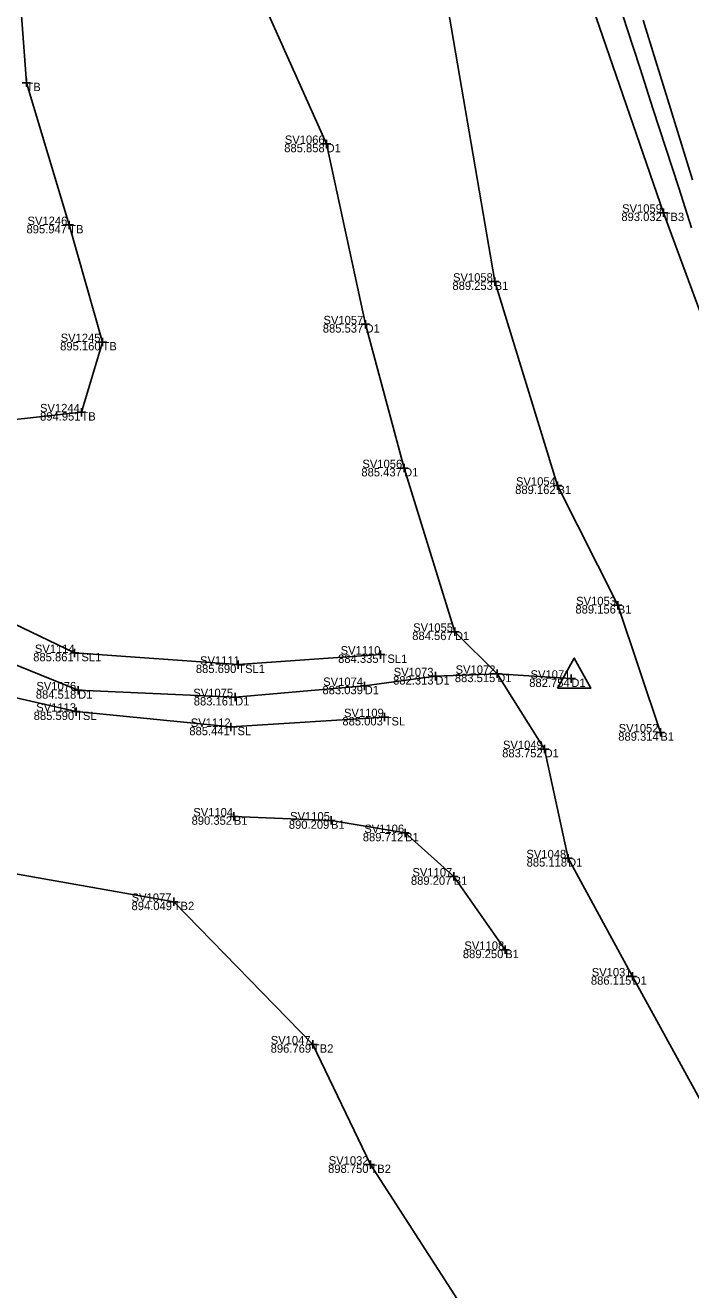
# Model space of a CAD drawing. Extents: x 1918148 to 1919797, y 624701 to 627089.
# Drawn here: x 1919158.7 to 1919238.3, y 625555 to 625706.2 of the extents above; entities that cross this region are included whole.
import ezdxf

# ---------------------------------------------------------------- set-up
doc = ezdxf.new("R2010")
doc.units = 0
for name, color, linetype in [('DR_X_Ditch', 7, 'Continuous'), ('LT_X_Control_Center', 7, 'Continuous'), ('PV_X_EOP', 7, 'Continuous'), ('PV_X_Shoulder_Aggregate', 7, 'Continuous'), ('SV_X_Break_Lines', 7, 'Continuous'), ('SV_X_Shot_Marker', 7, 'Continuous'), ('SV_X_Text_Comment', 7, 'Continuous'), ('SV_X_Text_Elevation', 7, 'Continuous'), ('SV_X_Text_Name', 7, 'Continuous'), ('SV_X_Toe_of_Slope', 7, 'Continuous'), ('SV_X_Top_of_Bank', 7, 'Continuous')]:
    doc.layers.add(name, color=color, linetype=linetype)

msp = doc.modelspace()

# ---------------------------------------------------------------- linework, layer by layer
at = {"layer": 'DR_X_Ditch'}
for points in [[(1919215.15, 625628.65), (1919210.09, 625633.68), (1919204.01, 625653.25), (1919199.4, 625670.45), (1919194.75, 625692.02), (1919183.69, 625716.71)], [(1919224, 625628.07), (1919215.15, 625628.65), (1919207.75, 625628.36), (1919199.3, 625627.2), (1919183.82, 625625.86), (1919165.06, 625626.67), (1919142.71, 625635.75), (1919122.83, 625635.23), (1919098.16, 625641.27), (1919077.76, 625644.25), (1919054.75, 625637.77), (1919041.67, 625636.77), (1919038.23, 625635.98), (1919036.3, 625636.3), (1919031.6, 625635.22)], [(1919294.9, 625444.11), (1919278.12, 625494.14), (1919254.13, 625550.83), (1919231.31, 625592.46), (1919223.61, 625606.59), (1919220.8, 625619.65), (1919215.15, 625628.65)]]:
    msp.add_lwpolyline(points, dxfattribs=at)
at = {"layer": 'LT_X_Control_Center'}
msp.add_lwpolyline([(1919222.35, 625626.94), (1919226.35, 625626.94), (1919224.35, 625630.53), (1919222.35, 625626.94)], dxfattribs=at)
at = {"layer": 'PV_X_EOP'}
msp.add_lwpolyline([(1919238.5, 625687.72), (1919237.02, 625692.5), (1919235.53, 625697.27), (1919234.05, 625702.05), (1919232.57, 625706.82)], dxfattribs=at)
at = {"layer": 'PV_X_Shoulder_Aggregate'}
msp.add_lwpolyline([(1919229.15, 625710.54), (1919230.69, 625705.78), (1919232.23, 625701.02), (1919233.76, 625696.26), (1919235.3, 625691.51), (1919236.84, 625686.75), (1919238.37, 625681.99)], dxfattribs=at)
at = {"layer": 'SV_X_Break_Lines'}
for points in [[(1919234.64, 625621.64), (1919229.55, 625636.85), (1919222.35, 625651.15), (1919214.84, 625675.55), (1919208.51, 625712.55), (1919200.45, 625729.66), (1919195.26, 625734.59), (1919183.77, 625729.69), (1919174.96, 625722.44)], [(1919183.67, 625611.59), (1919195.28, 625611.11), (1919204.14, 625609.61), (1919209.94, 625604.41), (1919216.1, 625595.64)]]:
    msp.add_lwpolyline(points, dxfattribs=at)
at = {"layer": 'SV_X_Shot_Marker'}
for p, q in [((1919158.88, 625699.83), (1919158.88, 625698.83)), ((1919158.38, 625699.33), (1919159.38, 625699.33)), ((1919158.88, 625699.33), (1919158.88, 625699.33)), ((1919194.75, 625692.52), (1919194.75, 625691.52)), ((1919194.25, 625692.02), (1919195.25, 625692.02)), ((1919194.75, 625692.02), (1919194.75, 625692.02)), ((1919234.53, 625683.79), (1919235.53, 625683.79)), ((1919235.03, 625684.29), (1919235.03, 625683.29)), ((1919235.03, 625683.79), (1919235.03, 625683.79)), ((1919163.49, 625682.32), (1919164.49, 625682.32)), ((1919163.99, 625682.82), (1919163.99, 625681.82)), ((1919163.99, 625682.32), (1919163.99, 625682.32)), ((1919214.84, 625676.05), (1919214.84, 625675.05)), ((1919214.34, 625675.55), (1919215.34, 625675.55)), ((1919214.84, 625675.55), (1919214.84, 625675.55)), ((1919198.9, 625670.45), (1919199.9, 625670.45)), ((1919199.4, 625670.95), (1919199.4, 625669.95)), ((1919199.4, 625670.45), (1919199.4, 625670.45)), ((1919167.47, 625668.32), (1919168.47, 625668.32)), ((1919167.97, 625668.82), (1919167.97, 625667.82)), ((1919167.97, 625668.32), (1919167.97, 625668.32)), ((1919164.95, 625659.92), (1919165.95, 625659.92)), ((1919165.45, 625660.42), (1919165.45, 625659.42)), ((1919165.45, 625659.92), (1919165.45, 625659.92)), ((1919203.51, 625653.25), (1919204.51, 625653.25)), ((1919204.01, 625653.75), (1919204.01, 625652.75)), ((1919204.01, 625653.25), (1919204.01, 625653.25)), ((1919222.35, 625651.65), (1919222.35, 625650.65)), ((1919221.85, 625651.15), (1919222.85, 625651.15)), ((1919222.35, 625651.15), (1919222.35, 625651.15)), ((1919229.05, 625636.85), (1919230.05, 625636.85)), ((1919229.55, 625637.35), (1919229.55, 625636.35)), ((1919229.55, 625636.85), (1919229.55, 625636.85)), ((1919209.59, 625633.68), (1919210.59, 625633.68)), ((1919210.09, 625634.18), (1919210.09, 625633.18)), ((1919210.09, 625633.68), (1919210.09, 625633.68)), ((1919164.13, 625631.14), (1919165.13, 625631.14)), ((1919164.63, 625631.64), (1919164.63, 625630.64)), ((1919164.63, 625631.14), (1919164.63, 625631.14)), ((1919184.19, 625630.24), (1919184.19, 625629.24)), ((1919200.7, 625630.95), (1919201.7, 625630.95)), ((1919201.2, 625631.45), (1919201.2, 625630.45)), ((1919201.2, 625630.95), (1919201.2, 625630.95)), ((1919183.69, 625629.74), (1919184.69, 625629.74)), ((1919184.19, 625629.74), (1919184.19, 625629.74)), ((1919207.75, 625628.86), (1919207.75, 625627.86)), ((1919215.15, 625629.15), (1919215.15, 625628.15)), ((1919198.8, 625627.2), (1919199.8, 625627.2)), ((1919199.3, 625627.7), (1919199.3, 625626.7)), ((1919199.3, 625627.2), (1919199.3, 625627.2)), ((1919207.25, 625628.36), (1919208.25, 625628.36)), ((1919207.75, 625628.36), (1919207.75, 625628.36)), ((1919214.65, 625628.65), (1919215.65, 625628.65)), ((1919215.15, 625628.65), (1919215.15, 625628.65)), ((1919223.5, 625628.07), (1919224.5, 625628.07)), ((1919224, 625628.57), (1919224, 625627.57)), ((1919224, 625628.07), (1919224, 625628.07)), ((1919164.56, 625626.67), (1919165.56, 625626.67)), ((1919165.06, 625627.17), (1919165.06, 625626.17)), ((1919165.06, 625626.67), (1919165.06, 625626.67)), ((1919183.32, 625625.86), (1919184.32, 625625.86)), ((1919183.82, 625626.36), (1919183.82, 625625.36)), ((1919183.82, 625625.86), (1919183.82, 625625.86)), ((1919164.81, 625624.62), (1919164.81, 625623.62)), ((1919164.31, 625624.12), (1919165.31, 625624.12)), ((1919164.81, 625624.12), (1919164.81, 625624.12)), ((1919183.29, 625622.8), (1919183.29, 625621.8)), ((1919201.19, 625623.47), (1919202.19, 625623.47)), ((1919201.69, 625623.97), (1919201.69, 625622.97)), ((1919201.69, 625623.47), (1919201.69, 625623.47)), ((1919182.79, 625622.3), (1919183.79, 625622.3)), ((1919183.29, 625622.3), (1919183.29, 625622.3)), ((1919234.14, 625621.64), (1919235.14, 625621.64)), ((1919234.64, 625622.14), (1919234.64, 625621.14)), ((1919234.64, 625621.64), (1919234.64, 625621.64)), ((1919220.3, 625619.65), (1919221.3, 625619.65)), ((1919220.8, 625620.15), (1919220.8, 625619.15)), ((1919220.8, 625619.65), (1919220.8, 625619.65)), ((1919183.67, 625612.09), (1919183.67, 625611.09)), ((1919183.17, 625611.59), (1919184.17, 625611.59)), ((1919183.67, 625611.59), (1919183.67, 625611.59)), ((1919194.78, 625611.11), (1919195.78, 625611.11)), ((1919195.28, 625611.61), (1919195.28, 625610.61)), ((1919195.28, 625611.11), (1919195.28, 625611.11)), ((1919203.64, 625609.61), (1919204.64, 625609.61)), ((1919204.14, 625610.11), (1919204.14, 625609.11)), ((1919204.14, 625609.61), (1919204.14, 625609.61)), ((1919223.11, 625606.59), (1919224.11, 625606.59)), ((1919223.61, 625607.09), (1919223.61, 625606.09)), ((1919223.61, 625606.59), (1919223.61, 625606.59)), ((1919209.94, 625604.91), (1919209.94, 625603.91)), ((1919209.44, 625604.41), (1919210.44, 625604.41)), ((1919209.94, 625604.41), (1919209.94, 625604.41)), ((1919176.48, 625601.88), (1919176.48, 625600.88)), ((1919175.98, 625601.38), (1919176.98, 625601.38)), ((1919176.48, 625601.38), (1919176.48, 625601.38)), ((1919215.6, 625595.64), (1919216.6, 625595.64)), ((1919216.1, 625596.14), (1919216.1, 625595.14)), ((1919216.1, 625595.64), (1919216.1, 625595.64)), ((1919230.81, 625592.46), (1919231.81, 625592.46)), ((1919231.31, 625592.96), (1919231.31, 625591.96)), ((1919231.31, 625592.46), (1919231.31, 625592.46)), ((1919192.61, 625584.33), (1919193.61, 625584.33)), ((1919193.11, 625584.83), (1919193.11, 625583.83)), ((1919193.11, 625584.33), (1919193.11, 625584.33)), ((1919199.49, 625569.95), (1919200.49, 625569.95)), ((1919199.99, 625570.45), (1919199.99, 625569.45)), ((1919199.99, 625569.95), (1919199.99, 625569.95))]:
    msp.add_line(p, q, dxfattribs=at)
at = {"layer": 'SV_X_Toe_of_Slope'}
for points in [[(1919201.2, 625630.95), (1919184.19, 625629.74), (1919164.63, 625631.14), (1919143.85, 625641.12), (1919121.9, 625641.82), (1919098.95, 625646.44), (1919070.56, 625648.44), (1919055.29, 625646.77), (1919046, 625648.09), (1919040.48, 625646.87), (1919038.11, 625645.62)], [(1919201.69, 625623.47), (1919183.29, 625622.3), (1919164.81, 625624.12), (1919141.22, 625629.5), (1919122.46, 625631.75), (1919096.93, 625636.65), (1919075.89, 625635.33), (1919063.89, 625633.35), (1919057.91, 625628.43), (1919056.85, 625624.76), (1919055.86, 625621.45), (1919055.54, 625619.91), (1919054.71, 625619.18), (1919053.99, 625619.56), (1919053.17, 625621.2), (1919049.54, 625623.6), (1919045.1, 625627.13), (1919039.1, 625629.63), (1919034.53, 625630.73)]]:
    msp.add_lwpolyline(points, dxfattribs=at)
at = {"layer": 'SV_X_Top_of_Bank'}
for points in [[(1919311.1, 625448.91), (1919294.98, 625498.61), (1919274.7, 625559.01), (1919260.24, 625603.73), (1919254.49, 625621.03), (1919244.11, 625659.16), (1919235.03, 625683.79), (1919222.11, 625721.27), (1919200.65, 625791.17)], [(1919008.68, 625701.6), (1919017.73, 625687.93), (1919021.83, 625676.64), (1919027.22, 625671.33), (1919042.19, 625668.18), (1919068.63, 625667.59), (1919096.2, 625663.51), (1919124.68, 625660.31), (1919151.38, 625658.36), (1919165.45, 625659.92), (1919167.97, 625668.32), (1919163.99, 625682.32), (1919158.88, 625699.33), (1919157.69, 625715.48), (1919158.89, 625735.48)], [(1919176.48, 625601.38), (1919142.91, 625607.31), (1919114.8, 625611.59), (1919094.66, 625615.23), (1919080.24, 625618.58), (1919071.18, 625616.65)], [(1919266.12, 625435.63), (1919242.4, 625482.18), (1919222.32, 625535.31), (1919199.99, 625569.95), (1919193.11, 625584.33), (1919176.48, 625601.38)]]:
    msp.add_lwpolyline(points, dxfattribs=at)

# ---------------------------------------------------------------- texts
at = {"layer": 'SV_X_Text_Comment'}
for s, p in [('TB', (1919158.88, 625698.33)), ('D1', (1919194.75, 625691.02)), ('TB3', (1919235.03, 625682.79)), ('TB', (1919163.99, 625681.32)), ('B1', (1919214.84, 625674.55)), ('D1', (1919199.4, 625669.45)), ('TB', (1919167.97, 625667.32)), ('TB', (1919165.45, 625658.93)), ('D1', (1919204.01, 625652.25)), ('B1', (1919222.35, 625650.15)), ('B1', (1919229.55, 625635.85)), ('D1', (1919210.09, 625632.68)), ('TSL1', (1919164.63, 625630.14)), ('TSL1', (1919201.2, 625629.95)), ('TSL1', (1919184.19, 625628.74)), ('D1', (1919199.3, 625626.2)), ('D1', (1919207.75, 625627.36)), ('D1', (1919215.15, 625627.65)), ('D1', (1919224, 625627.07)), ('D1', (1919165.06, 625625.67)), ('D1', (1919183.82, 625624.86)), ('TSL', (1919164.81, 625623.12)), ('TSL', (1919201.69, 625622.47)), ('TSL', (1919183.29, 625621.3)), ('B1', (1919234.64, 625620.64)), ('D1', (1919220.8, 625618.65)), ('B1', (1919183.67, 625610.59)), ('B1', (1919195.28, 625610.11)), ('B1', (1919204.14, 625608.61)), ('D1', (1919223.61, 625605.59)), ('B1', (1919209.94, 625603.41)), ('TB2', (1919176.48, 625600.38)), ('B1', (1919216.1, 625594.64)), ('D1', (1919231.31, 625591.46)), ('TB2', (1919193.11, 625583.33)), ('TB2', (1919199.99, 625568.95))]:
    msp.add_text(s, height=1, dxfattribs=at).set_placement(p)
at = {"layer": 'SV_X_Text_Elevation'}
for s, p in [('885.858', (1919189.69, 625691.02)), ('893.032', (1919229.98, 625682.79)), ('895.947', (1919158.89, 625681.32)), ('889.253', (1919209.79, 625674.55)), ('885.537', (1919194.3, 625669.45)), ('895.160', (1919162.91, 625667.32)), ('894.951', (1919160.51, 625658.93)), ('885.437', (1919198.91, 625652.25)), ('889.162', (1919217.29, 625650.15)), ('889.156', (1919224.49, 625635.85)), ('884.567', (1919204.99, 625632.68)), ('885.861', (1919159.69, 625630.14)), ('884.335', (1919196.13, 625629.95)), ('885.690', (1919179.13, 625628.74)), ('883.039', (1919194.26, 625626.2)), ('882.313', (1919202.7, 625627.36)), ('883.515', (1919210.08, 625627.65)), ('882.754', (1919218.97, 625627.07)), ('884.518', (1919160, 625625.67)), ('883.161', (1919178.88, 625624.86)), ('885.590', (1919159.75, 625623.12)), ('885.003', (1919196.64, 625622.47)), ('885.441', (1919178.35, 625621.3)), ('889.314', (1919229.61, 625620.64)), ('883.752', (1919215.74, 625618.65)), ('890.352', (1919178.62, 625610.59)), ('890.209', (1919190.24, 625610.11)), ('889.712', (1919199.08, 625608.61)), ('885.118', (1919218.66, 625605.59)), ('889.207', (1919204.83, 625603.41)), ('894.049', (1919171.44, 625600.38)), ('889.250', (1919211.04, 625594.64)), ('886.115', (1919226.34, 625591.46)), ('896.769', (1919188.07, 625583.33)), ('898.750', (1919194.93, 625568.95))]:
    msp.add_text(s, height=1, dxfattribs=at).set_placement(p)
at = {"layer": 'SV_X_Text_Name'}
for s, p in [('SV1066', (1919189.76, 625692.02)), ('SV1059', (1919230.07, 625683.79)), ('SV1246', (1919159.01, 625682.32)), ('SV1058', (1919209.86, 625675.55)), ('SV1057', (1919194.38, 625670.45)), ('SV1245', (1919162.97, 625668.32)), ('SV1244', (1919160.5, 625659.92)), ('SV1056', (1919199.03, 625653.25)), ('SV1054', (1919217.39, 625651.15)), ('SV1053', (1919224.58, 625636.85)), ('SV1055', (1919205.1, 625633.68)), ('SV1114', (1919159.89, 625631.14)), ('SV1110', (1919196.43, 625630.95)), ('SV1111', (1919179.63, 625629.74)), ('SV1073', (1919202.77, 625628.36)), ('SV1072', (1919210.17, 625628.65)), ('SV1071', (1919219.13, 625628.07)), ('SV1076', (1919160.07, 625626.67)), ('SV1074', (1919194.35, 625627.2)), ('SV1075', (1919178.82, 625625.86)), ('SV1113', (1919160.05, 625624.12)), ('SV1109', (1919196.83, 625623.47)), ('SV1112', (1919178.52, 625622.3)), ('SV1052', (1919229.66, 625621.64)), ('SV1049', (1919215.83, 625619.65)), ('SV1104', (1919178.82, 625611.59)), ('SV1105', (1919190.39, 625611.11)), ('SV1106', (1919199.26, 625609.61)), ('SV1048', (1919218.63, 625606.59)), ('SV1107', (1919205.01, 625604.41)), ('SV1077', (1919171.45, 625601.38)), ('SV1108', (1919211.22, 625595.64)), ('SV1031', (1919226.44, 625592.46)), ('SV1047', (1919188.08, 625584.33)), ('SV1032', (1919195.01, 625569.95))]:
    msp.add_text(s, height=1, dxfattribs=at).set_placement(p)

doc.saveas('drawing.dxf')
